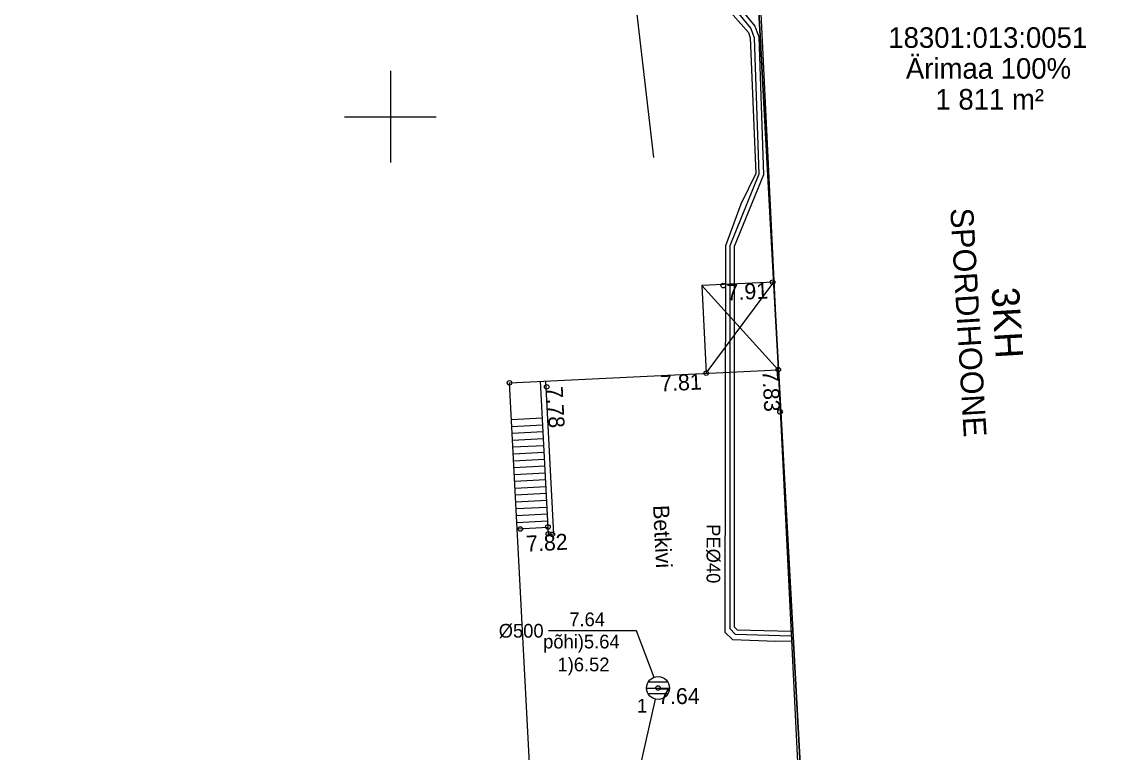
# Model space of a CAD drawing. Extents: x 473307 to 473719, y 6532843 to 6533381.
# Drawn here: x 473533.89 to 473582.18, y 6533222.19 to 6533254.14 of the extents above; entities that cross this region are included whole.
import ezdxf

# ---------------------------------------------------------------- set-up
doc = ezdxf.new("R2010")
doc.units = 0
for name, color, linetype in [('Default', 7, 'Continuous'), ('HOONE', 7, 'Continuous'), ('HOONEDET', 7, 'Continuous'), ('KORGUS', 7, 'Continuous'), ('MPKAABEL', 7, 'Continuous'), ('PIIR', 7, 'Continuous'), ('SKKAEV', 7, 'Continuous'), ('SKKAEV_NR', 7, 'Continuous'), ('SKTRASS', 7, 'Continuous'), ('TEE', 7, 'Continuous'), ('VORK', 7, 'Continuous'), ('VTRASS', 7, 'Continuous'), ('VTRASS_TEKST', 7, 'Continuous')]:
    doc.layers.add(name, color=color, linetype=linetype)

# ---------------------------------------------------------------- blocks, each defined once
blk = doc.blocks.new('REKAEV')
at = {"layer": 'Default'}
for p, q in [((-1, 0), (1, 0)), ((0.86, 0.5), (-0.86, 0.5)), ((0.86, -0.5), (-0.86, -0.5))]:
    blk.add_line(p, q, dxfattribs=at)
blk.add_circle((0, 0), 1, dxfattribs=at)
blk = doc.blocks.new('VKORIS')
at = {"layer": 'Default'}
for p, q in [((0, 4), (0, -4)), ((-4, 0), (4, 0))]:
    blk.add_line(p, q, dxfattribs=at)

msp = doc.modelspace()

# ---------------------------------------------------------------- linework, layer by layer
at = {"layer": 'HOONE'}
for points in [[(473586.451, 6533222.028), (473586.163, 6533228.83), (473590.126, 6533228.998), (473589.07, 6533252.381), (473588.538, 6533252.355), (473587.928, 6533265.086), (473574.864, 6533264.513), (473574.621, 6533270.17), (473553.465, 6533269.148), (473553.468, 6533269.088), (473497.143, 6533266.366), (473498.091, 6533246.719), (473499.996, 6533208.142), (473556.654, 6533210.892), (473555.213, 6533238.366), (473566.97, 6533238.94), (473567.826, 6533221.491), (473567.7, 6533221.486), (473567.712, 6533221.234), (473586.451, 6533222.028)], [(473574.864, 6533264.513), (473565.735, 6533264.112), (473566.97, 6533238.94)], [(473566.782, 6533242.768), (473563.631, 6533242.616), (473563.815, 6533238.786)]]:
    msp.add_lwpolyline(points, dxfattribs=at)
at = {"layer": 'HOONEDET'}
for points in [[(473563.631, 6533242.616), (473566.97, 6533238.94)], [(473563.815, 6533238.786), (473566.782, 6533242.768)], [(473556.785, 6533238.443), (473557.136, 6533231.744), (473556.914, 6533231.733), (473556.898, 6533232.038), (473555.548, 6533231.967)], [(473556.898, 6533232.038), (473556.562, 6533238.432)], [(473555.297, 6533236.761), (473556.646, 6533236.831)], [(473555.313, 6533236.461), (473556.662, 6533236.532)], [(473555.328, 6533236.161), (473556.678, 6533236.232)], [(473555.344, 6533235.862), (473556.693, 6533235.933)], [(473555.36, 6533235.562), (473556.709, 6533235.633)], [(473555.376, 6533235.263), (473556.725, 6533235.333)], [(473555.391, 6533234.963), (473556.741, 6533235.034)], [(473555.407, 6533234.664), (473556.756, 6533234.734)], [(473555.423, 6533234.364), (473556.772, 6533234.435)], [(473555.438, 6533234.064), (473556.788, 6533234.135)], [(473555.454, 6533233.765), (473556.803, 6533233.836)], [(473555.47, 6533233.465), (473556.819, 6533233.536)], [(473555.486, 6533233.166), (473556.835, 6533233.236)], [(473555.501, 6533232.866), (473556.851, 6533232.937)], [(473555.517, 6533232.566), (473556.866, 6533232.637)], [(473555.533, 6533232.267), (473556.882, 6533232.338)]]:
    msp.add_lwpolyline(points, dxfattribs=at)
at = {"layer": 'KORGUS'}
for centre in [(473564.565, 6533242.618), (473566.723, 6533242.765), (473563.815, 6533238.786), (473566.97, 6533238.94), (473555.213, 6533238.366), (473556.838, 6533238.192), (473567.049, 6533237.095), (473555.688, 6533231.975), (473556.894, 6533232.066), (473556.912, 6533231.767), (473557.082, 6533231.741), (473561.712, 6533225.023)]:
    msp.add_circle(centre, 0.1, dxfattribs=at)
at = {"layer": 'MPKAABEL'}
for points in [[(473542.034, 6533294.523), (473549.77, 6533277.94), (473555.143, 6533270.091), (473555.526, 6533269.435), (473556.291, 6533268.996), (473557.105, 6533268.695), (473558.02, 6533267.83), (473559.509, 6533265.389), (473561.517, 6533248.21)], [(473480.365, 6533268.27), (473486.968, 6533270.185), (473505.108, 6533271.242), (473522.107, 6533272.232), (473536.546, 6533272.905), (473546.795, 6533273.053), (473554.248, 6533270.36), (473561.825, 6533270.623), (473562.911, 6533270.389), (473563.404, 6533268.093), (473564.172, 6533264.458), (473564.376, 6533256.129), (473564.597, 6533255.606), (473565.945, 6533253.956), (473566.12, 6533253.49), (473566.326, 6533247.459), (473565.047, 6533244.322), (473565.048, 6533227.704), (473565.17, 6533227.573), (473567.534, 6533227.504)], [(473480.421, 6533268.078), (473487.002, 6533269.987), (473505.119, 6533271.042), (473522.118, 6533272.033), (473536.552, 6533272.705), (473546.761, 6533272.852), (473554.217, 6533270.159), (473561.807, 6533270.422), (473562.743, 6533270.221), (473563.208, 6533268.051), (473563.972, 6533264.435), (473564.177, 6533256.086), (473564.424, 6533255.502), (473565.77, 6533253.855), (473565.921, 6533253.45), (473566.125, 6533247.495), (473564.847, 6533244.361), (473564.848, 6533227.626), (473565.081, 6533227.375), (473567.528, 6533227.304)]]:
    msp.add_lwpolyline(points, dxfattribs=at)
at = {"layer": 'PIIR'}
for points in [[(473586.5, 6533271.93), (473601.56, 6533272.81), (473609.94, 6533222.84), (473586.39, 6533221.76), (473567.96, 6533221.17), (473565.61, 6533263.9), (473587.68, 6533264.9)], [(473496.37, 6533266.79), (473586.5, 6533271.93), (473587.68, 6533264.9), (473565.61, 6533263.9), (473567.96, 6533221.17), (473558.63, 6533220.73), (473559.2, 6533209.37), (473499.84, 6533206.38)]]:
    msp.add_lwpolyline(points, close=True, dxfattribs=at)
at = {"layer": 'SKKAEV_NR'}
msp.add_lwpolyline([(473561.536, 6533225.491), (473560.768, 6533227.526), (473556.913, 6533227.526)], dxfattribs=at)
at = {"layer": 'SKTRASS'}
msp.add_lwpolyline([(473557.974, 6533208.401), (473561.602, 6533224.536)], dxfattribs=at)
at = {"layer": 'VTRASS'}
msp.add_lwpolyline([(473556.042, 6533281.885), (473556.042, 6533281.885), (473556.978, 6533268.765), (473562.32, 6533269.051), (473562.875, 6533268.905), (473563.261, 6533268.223), (473563.768, 6533264.181), (473563.973, 6533255.805), (473564.331, 6533255.208), (473565.662, 6533253.682), (473565.74, 6533253.452), (473565.996, 6533247.522), (473565.333, 6533246.179), (473564.656, 6533244.354), (473564.656, 6533244.354), (473564.635, 6533227.469), (473564.961, 6533227.145), (473566.871, 6533227.066), (473567.538, 6533227.089)], dxfattribs=at)

# ---------------------------------------------------------------- block references
at = {"layer": 'SKKAEV', "xscale": 0.5, "yscale": 0.5}
msp.add_blockref('REKAEV', (473561.712, 6533225.023), dxfattribs=at)
at = {"layer": 'VORK', "xscale": 0.5, "yscale": 0.5}
msp.add_blockref('VKORIS', (473550, 6533250), dxfattribs=at)

# ---------------------------------------------------------------- texts
at = {"layer": 'HOONE'}
for s, height, p in [('SPORDIHOONE', 1, (473574.494, 6533245.985)), ('3KH', 1.2, (473576.303, 6533242.516))]:
    msp.add_text(s, height=height, rotation=273.4053, dxfattribs=at).set_placement(p)
at = {"layer": 'KORGUS'}
for s, rotation, p in [('7.91', 2.7457, (473564.725, 6533241.968)), ('7.81', 2.796, (473561.818, 6533237.988)), ('7.83', 272.8081, (473566.271, 6533238.906)), ('7.78', 273.0017, (473556.838, 6533238.192)), ('7.82', 3.0017, (473555.954, 6533230.981))]:
    msp.add_text(s, height=0.7, rotation=rotation, dxfattribs=at).set_placement(p)
msp.add_text('7.64', height=0.7, dxfattribs=at).set_placement((473561.712, 6533224.323))
at = {"layer": 'PIIR'}
for s, p in [('18301:013:0051', (473571.784, 6533253.011)), ('Ärimaa 100%', (473572.554, 6533251.661)), ('1 811 m²', (473573.847, 6533250.311))]:
    msp.add_text(s, height=0.9, dxfattribs=at).set_placement(p)
at = {"layer": 'SKKAEV_NR'}
for s, p in [('7.64', (473557.827, 6533227.726)), ('%%C500', (473554.742, 6533227.226)), ('põhi)5.64', (473556.684, 6533226.754)), ('1)6.52', (473557.312, 6533225.754)), ('1', (473560.79, 6533223.95))]:
    msp.add_text(s, height=0.6, dxfattribs=at).set_placement(p)
at = {"layer": 'TEE'}
msp.add_text('Betkivi', height=0.7, rotation=272.8081, dxfattribs=at).set_placement((473561.491, 6533233.005))
at = {"layer": 'VTRASS_TEKST'}
msp.add_text('PE%%C40', height=0.6, rotation=269.9293, dxfattribs=at).set_placement((473563.835, 6533232.189))

doc.saveas('drawing.dxf')
